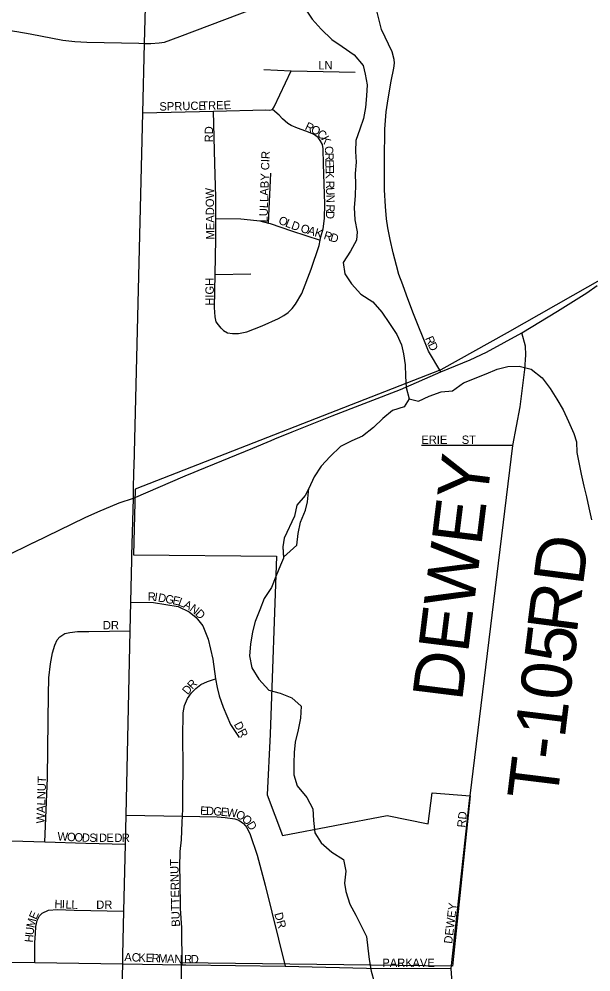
# Model space of a CAD drawing. Extents: x 1857828 to 2277390, y 930619 to 1324581.
# Drawn here: x 2047591 to 2051013, y 1238040 to 1243739 of the extents above; entities that cross this region are included whole.
import ezdxf

# ---------------------------------------------------------------- set-up
doc = ezdxf.new("R2010")
doc.units = 0
for name, color, linetype in [('GM_X_City_Street', 7, 'Continuous'), ('GM_X_City_Street_Text', 7, 'Continuous'), ('GM_X_Corporation', 7, 'Continuous'), ('GM_X_County_Road', 7, 'Continuous'), ('GM_X_Interchange_Ramps', 7, 'Continuous'), ('GM_X_Minor_Lake', 7, 'Continuous'), ('GM_X_Minor_River', 7, 'Continuous'), ('GM_X_State_Route', 7, 'Continuous'), ('GM_X_Township_Road', 7, 'Continuous'), ('GM_X_Township_Road_Text', 7, 'Continuous'), ('GM_X_Township_Subdivision', 7, 'Continuous'), ('GM_X_Township_Subdivision_Text', 7, 'Continuous')]:
    doc.layers.add(name, color=color, linetype=linetype)

msp = doc.modelspace()

# ---------------------------------------------------------------- linework, layer by layer
at = {"layer": 'GM_X_City_Street'}
for points in [[(2050114.3, 1241629.1), (2050041.6, 1241751.9), (2049947.3, 1241986.2), (2049910.3, 1242088.3), (2049887.7, 1242148.4), (2049863.1, 1242210.5), (2049850.6, 1242264.6), (2049829.9, 1242340.8), (2049811.2, 1242421), (2049798.6, 1242489.1), (2049790.1, 1242543.3), (2049783.4, 1242617.6), (2049778.5, 1242717.9), (2049777, 1242896.6), (2049779.4, 1243079.4), (2049788.6, 1243183.9), (2049799.9, 1243262.3), (2049817.1, 1243366.8), (2049834.5, 1243445.3), (2049838.2, 1243475.4), (2049836, 1243497.5), (2049823.6, 1243543.6), (2049760.2, 1243675.7), (2049725, 1243819.8)], [(2048332.3, 1243178.8), (2048755.6, 1243188), (2049068.5, 1243194.8), (2049092.6, 1243193), (2049108.6, 1243197.1), (2049118.4, 1243213.2), (2049218.9, 1243428.8), (2049602, 1243421.5)], [(2049056.3, 1243437.7), (2049218.9, 1243428.8)], [(2048801, 1241889.6), (2048815.1, 1241875.6), (2048839.3, 1241861.8), (2048869.4, 1241857.9), (2048903.5, 1241858.2), (2048953.5, 1241868.6), (2049045.5, 1241903.4), (2049143.4, 1241948.3), (2049175.3, 1241966.6), (2049201.2, 1241982.8), (2049225.1, 1242007.1), (2049245, 1242033.3), (2049282.5, 1242097.9), (2049339.4, 1242242.9), (2049386.3, 1242383.8), (2049393.7, 1242417.1), (2049397.9, 1242436.1), (2049411.5, 1242484.4), (2049419, 1242546.7), (2049420.3, 1242633), (2049412.2, 1242869.9), (2049411.4, 1242962.3), (2049407.2, 1242988.4), (2049392.9, 1243012.4), (2049380.7, 1243030.4), (2049352.5, 1243050.2), (2049308.2, 1243068), (2049257.9, 1243085.7), (2049219.7, 1243101.5), (2049199.5, 1243113.4), (2049167.2, 1243141.3), (2049147, 1243163.2), (2049108.6, 1243197.1)], [(2048801, 1241889.6), (2048784.7, 1241909.6), (2048770.5, 1241927.5), (2048764.3, 1241957.6), (2048761.7, 1242013.8), (2048764.9, 1242210.7), (2048768.3, 1242421.5), (2048769.3, 1242540), (2048769.2, 1242546), (2048768.1, 1242672.5), (2048762.4, 1242875.3), (2048755.6, 1243188)], [(2049084.4, 1242518.7), (2049097.8, 1242817.5)], [(2048769.2, 1242546), (2048917.7, 1242543.1), (2048975.9, 1242537.4), (2049032.1, 1242531.8), (2049084.4, 1242518.7), (2049094.4, 1242516.2), (2049221.1, 1242472.9), (2049393.7, 1242417.1)], [(2048764.9, 1242210.7), (2048978.6, 1242214.1)], [(2050599.4, 1241861.1), (2050813.1, 1241991.1), (2050988.2, 1242101.5), (2051051, 1242145.6)], [(2049100.5, 1241219), (2049121.8, 1241227.9), (2049224.6, 1241270.8), (2049465.7, 1241364.8), (2049873.3, 1241522.8), (2050114.3, 1241629.1), (2050291.1, 1241700.9), (2050387.5, 1241747), (2050599.4, 1241861.1)], [(2048662.4, 1241038.2), (2048989.7, 1241172.8), (2049100.5, 1241219)], [(2047680.6, 1240608.2), (2047987.5, 1240756.7), (2048063.8, 1240790.7), (2048190.3, 1240844.7), (2048275.3, 1240872.4)], [(2046329.7, 1239926.7), (2046368.7, 1239947.8), (2046563.8, 1240050.7), (2046760.3, 1240150.1), (2047028.5, 1240284.5), (2047208, 1240368.8), (2047507.5, 1240524.5), (2047678.9, 1240607.4), (2047680.6, 1240608.2)], [(2048260.5, 1240250.8), (2048395.9, 1240250.1), (2048542.5, 1240225), (2048609, 1240193.4), (2048651.4, 1240159.5), (2048691.9, 1240109.6), (2048722.7, 1240029.5), (2048751.8, 1239909.3), (2048767, 1239792.5), (2048777.4, 1239740.8), (2048787.8, 1239690.6), (2048812.5, 1239622.6), (2048857.5, 1239520.5), (2048908.3, 1239442.5)], [(2047746.6, 1238816.8), (2047761.2, 1239199.3), (2047766.2, 1239542.7), (2047766.9, 1239697.4), (2047770.1, 1239797.8), (2047779.4, 1239882.2), (2047790.8, 1239948.5), (2047806.5, 1239994.9), (2047820.2, 1240025), (2047836.1, 1240043.3), (2047866, 1240063.5), (2047896.1, 1240069.8), (2047942.1, 1240076.1), (2048008.3, 1240076.6), (2048256.7, 1240079.8)], [(2048566.5, 1238082.4), (2048565.1, 1238303.5), (2048558.1, 1238419.9), (2048554.6, 1238588.5), (2048553.9, 1238666.8), (2048555.2, 1238759.2), (2048562.6, 1238829.6), (2048567.7, 1238936), (2048569.2, 1238971.4), (2048571, 1239014.4), (2048572.3, 1239100.7), (2048572.8, 1239273.4), (2048571.3, 1239442.1), (2048574.1, 1239588.7), (2048581.7, 1239632.9), (2048599.4, 1239675.2), (2048623.2, 1239709.5), (2048649.1, 1239735.8), (2048678.9, 1239758.1), (2048718.9, 1239776.5), (2048767, 1239792.5)], [(2050175.8, 1238060.8), (2050286.8, 1239065.8)], [(2048231.9, 1238977.4), (2048569.2, 1238971.4), (2048776, 1238967.7), (2048824.2, 1238964), (2048882.4, 1238956.3), (2048906.5, 1238946.5), (2048934.8, 1238926.6), (2048955.1, 1238902.7), (2048973.4, 1238862.6), (2049016.6, 1238738.4), (2049064.3, 1238558.1), (2049184.5, 1238073.8)], [(2047280.7, 1238830.9), (2047746.6, 1238816.8), (2047991.2, 1238809.4), (2048228, 1238804.4)], [(2047686.1, 1238095.4), (2047685.4, 1238214.8), (2047689, 1238269.1), (2047692.6, 1238311.3), (2047700.3, 1238347.5), (2047714.1, 1238375.7), (2047730, 1238391.8), (2047768, 1238408.2), (2047822.1, 1238412.6), (2047920.4, 1238409.3), (2048218.9, 1238402.8)], [(2044269.9, 1238136.2), (2044270.6, 1238136.2), (2044643.1, 1238131.7), (2044937.6, 1238128.2), (2045323.7, 1238123.6), (2045700.7, 1238119.1), (2046048.1, 1238114.9), (2046166.6, 1238113.5), (2046555.1, 1238108.9), (2047004.4, 1238103.5), (2047317.3, 1238099.8), (2047686.1, 1238095.4), (2048211.9, 1238089.1)], [(2048211.9, 1238089.1), (2048566.5, 1238082.4), (2048589.9, 1238082)], [(2049669.9, 1238061.4), (2050175.8, 1238060.8)]]:
    msp.add_lwpolyline(points, dxfattribs=at)
at = {"layer": 'GM_X_Corporation'}
msp.add_lwpolyline([(2054519.4, 1244972.1), (2052959.6, 1243661.5), (2051504, 1242516), (2051093.4, 1242193.8), (2050512.1, 1241862.8), (2050115.7, 1241640.1), (2048286.1, 1240927.9), (2048275.3, 1240533.9), (2049131.1, 1240525.7), (2049093, 1239461.4), (2049075.6, 1239098), (2049168.6, 1238855), (2049793.9, 1238975.3), (2050039.3, 1238925.1), (2050063.1, 1239111.8), (2050289.8, 1239093.4), (2050184.9, 1238073.5), (2048562, 1238095.1), (2048562, 1237508.6)], dxfattribs=at)
at = {"layer": 'GM_X_County_Road'}
msp.add_lwpolyline([(2048275.3, 1240872.4), (2048586, 1241006.7), (2048638.4, 1241028.3), (2048662.4, 1241038.2)], dxfattribs=at)
at = {"layer": 'GM_X_Interchange_Ramps'}
for points in [[(2048342.5, 1243593.2), (2048380.3, 1243592.3), (2048429.2, 1243595.8), (2048462.6, 1243600.8), (2048554.3, 1243634.7), (2049001.7, 1243803.6), (2049097.6, 1243838.3), (2049191.4, 1243864.8), (2049287.3, 1243889.3), (2049379, 1243905.6), (2049486.7, 1243920.4), (2049481.9, 1243984.8)], [(2047343.5, 1243756.3), (2047352.1, 1243688.2), (2047394.3, 1243687.3), (2047486.1, 1243679.1), (2047577.9, 1243664.8), (2047657.5, 1243650.6), (2047853.3, 1243611.8), (2047924.7, 1243603.6), (2047996.1, 1243599.5), (2048308.3, 1243594), (2048342.5, 1243593.2)]]:
    msp.add_lwpolyline(points, dxfattribs=at)
at = {"layer": 'GM_X_Minor_Lake'}
for points in [[(2049324.8, 1240931.6), (2049303.1, 1240889.2), (2049253.4, 1240830.6), (2049239.9, 1240766.2), (2049176.8, 1240633.2), (2049169.2, 1240582.9), (2049173.5, 1240519.4)], [(2049324.8, 1240931.6), (2049303.1, 1240889.2), (2049253.4, 1240830.6), (2049239.9, 1240766.2), (2049176.8, 1240633.2), (2049169.2, 1240582.9), (2049173.8, 1240514.6)], [(2049173.5, 1240519.4), (2049253.4, 1240591.6), (2049260.9, 1240661.9), (2049276.3, 1240730.3), (2049305.9, 1240800.9), (2049317.5, 1240851.2), (2049324.8, 1240931.6)]]:
    msp.add_lwpolyline(points, dxfattribs=at)
at = {"layer": 'GM_X_Minor_River'}
for points in [[(2049300.3, 1243804.6), (2049345, 1243738.6), (2049399.7, 1243678.6), (2049462.5, 1243616.8), (2049525.1, 1243575), (2049595.8, 1243525.3), (2049650.5, 1243461.4), (2049663, 1243409.2), (2049673.6, 1243345), (2049670.2, 1243278.7), (2049664.7, 1243210.3), (2049653.2, 1243143.9)], [(2049653.2, 1243143.9), (2049629.7, 1243079.5), (2049606.2, 1243013), (2049604.7, 1242946.7), (2049609.3, 1242882.4), (2049601.8, 1242814.1), (2049604.4, 1242749.8), (2049603, 1242681.5), (2049595.6, 1242611.1), (2049600.2, 1242538.8), (2049614.9, 1242466.6), (2049611.3, 1242416.3), (2049573.7, 1242349.8), (2049530.1, 1242283.1), (2049540.7, 1242214.9), (2049581.4, 1242154.9), (2049636.1, 1242093), (2049708.8, 1242047.3), (2049761.5, 1241985.4), (2049808.3, 1241917.4), (2049851, 1241851.4), (2049879.6, 1241789.3), (2049892.1, 1241737.1), (2049900.7, 1241670.9), (2049903.3, 1241602.6), (2049907.9, 1241534.3), (2049924.5, 1241468.1)], [(2049924.5, 1241468.1), (2049980.9, 1241452.4), (2050044.8, 1241483), (2050116.9, 1241509.6), (2050185.1, 1241516.1), (2050250.9, 1241562.8), (2050387, 1241615.9), (2050451, 1241644.5), (2050515.1, 1241661), (2050583.3, 1241663.5), (2050655.8, 1241643.9), (2050720.5, 1241592.1), (2050769.2, 1241530.1), (2050809.9, 1241466.1), (2050846.5, 1241402.1), (2050879.3, 1241332), (2050910, 1241259.9), (2050926.5, 1241209.7), (2050929, 1241145.5), (2050954.2, 1241017.1), (2050970.9, 1240944.8), (2050985.5, 1240880.6), (2051000.1, 1240814.4), (2051016.8, 1240744.2)], [(2049924.5, 1241468.1), (2049894.8, 1241419.7), (2049826.7, 1241397.1), (2049768.9, 1241350.5), (2049711.2, 1241295.9), (2049645.4, 1241243.2), (2049583.4, 1241216.6), (2049515.4, 1241182), (2049453.7, 1241123.3), (2049398, 1241064.7), (2049356.3, 1241000.1), (2049324.8, 1240931.6)], [(2049173.8, 1240514.6), (2049156.1, 1240472.3), (2049128.6, 1240403.8), (2049101, 1240339.4), (2049057.4, 1240272.8), (2049031.9, 1240206.3), (2049004.4, 1240135.8), (2048988.8, 1240073.4), (2048975.4, 1240001), (2048970, 1239930.6), (2048984.7, 1239858.4), (2049025.4, 1239790.3), (2049086.2, 1239724.5), (2049154.6, 1239706.8), (2049223.1, 1239679.2), (2049279.7, 1239629.3), (2049276.3, 1239557), (2049260.8, 1239488.6), (2049243.4, 1239414.1), (2049237.9, 1239351.8), (2049234.5, 1239287.5), (2049235, 1239219.2), (2049255.7, 1239153), (2049312.5, 1239083.1), (2049349.2, 1239015), (2049353.8, 1238944.7), (2049360.5, 1238872.5), (2049399.1, 1238812.4), (2049463.8, 1238756.6), (2049532.5, 1238712.9), (2049547.1, 1238642.7), (2049537.7, 1238570.3), (2049546.2, 1238520.1), (2049570.9, 1238445.9), (2049605.6, 1238379.9), (2049670.9, 1238251.8), (2049677.5, 1238181.5), (2049686.1, 1238113.2), (2049698.8, 1238045), (2049715.4, 1237980.8)]]:
    msp.add_lwpolyline(points, dxfattribs=at)
at = {"layer": 'GM_X_State_Route'}
for points in [[(2048279.2, 1241032.4), (2048280, 1241062.7), (2048332.3, 1243178.8), (2048342.5, 1243593.2), (2048349.7, 1243883.2)], [(2048276.6, 1240925.7), (2048279.2, 1241032.4)], [(2048266.2, 1240504.8), (2048266.8, 1240530.6), (2048275.3, 1240872.4), (2048276.6, 1240925.7)], [(2048213.1, 1238141.6), (2048218.9, 1238402.8), (2048228, 1238804.4), (2048231.9, 1238977.4), (2048256.7, 1240079.8), (2048260.5, 1240250.8), (2048266.2, 1240504.8)], [(2048195.6, 1237502.7), (2048211.9, 1238089.1), (2048213.1, 1238141.6)]]:
    msp.add_lwpolyline(points, dxfattribs=at)
at = {"layer": 'GM_X_Township_Road'}
for points in [[(2050286.8, 1239065.8), (2050289.8, 1239093.4), (2050546.5, 1241188.9), (2050589.5, 1241420.1), (2050617.8, 1241643.7), (2050623.2, 1241731.2), (2050621.9, 1241782.4), (2050599.4, 1241861.1)], [(2048589.9, 1238082), (2049184.5, 1238073.8), (2049669.9, 1238061.4)], [(2050417.1, 1235061.1), (2050295.9, 1235126), (2050203.2, 1235192.5), (2050158.9, 1235238.9), (2050052.1, 1235400.1), (2050005.8, 1235486.7), (2049976.6, 1235543.2), (2049973.5, 1235627.8), (2049979.6, 1235839.4), (2049989.7, 1236004.2), (2050072.2, 1236844), (2050098.5, 1237032.8), (2050146.8, 1237207.3), (2050175, 1237312.9), (2050192.4, 1237414.3), (2050198, 1237519.7), (2050203.5, 1237628.9), (2050196.1, 1237777.9), (2050175.8, 1238060.8)]]:
    msp.add_lwpolyline(points, dxfattribs=at)
at = {"layer": 'GM_X_Township_Subdivision'}
msp.add_lwpolyline([(2050546.5, 1241188.9), (2049999, 1241187.6)], dxfattribs=at)

# ---------------------------------------------------------------- texts
at = {"layer": 'GM_X_City_Street_Text'}
for s, rotation, p in [('LN', 0, (2049381.9, 1243437.3)), ('TREE', 1.6357, (2048682.1, 1243195.3)), ('SPRUCE', 1.1011, (2048431.4, 1243190.9)), ('RD', 90, (2048752.2, 1243001.1)), ('R', 334.0648, (2049297.5, 1243080.3)), ('O', 334.0645, (2049333.1, 1243062.9)), ('C', 319.0563, (2049369.8, 1243045.6)), ('K', 298.8338, (2049396.7, 1243023.3)), ('C', 274.3279, (2049419.7, 1242977.3)), ('LULLABY CIR', 88.1104, (2049077.7, 1242521.8)), ('R', 271.7975, (2049422.6, 1242938.4)), ('E', 271.5031, (2049423.9, 1242898.9)), ('E', 271.5031, (2049424.8, 1242863.7)), ('K', 271.5086, (2049425.7, 1242828.5)), ('R', 271.5137, (2049427.2, 1242771.3)), ('MEADOW', 90.7646, (2048760.9, 1242420.5)), ('U', 271.5136, (2049428.2, 1242731.7)), ('N', 271.3338, (2049429.4, 1242687.8)), ('R', 267.7899, (2049430.4, 1242631.4)), ('D', 267.5522, (2049428.9, 1242591.9)), ('O', 337.2406, (2049139.2, 1242517)), ('L', 337.6341, (2049180.1, 1242499.8)), ('D', 341.4081, (2049216, 1242485.1)), ('O', 342.9905, (2049271.8, 1242466.8)), ('A', 342.9616, (2049313.8, 1242453.9)), ('K', 342.9616, (2049355.9, 1242441)), ('R', 342.9947, (2049410.6, 1242424.2)), ('D', 342.9616, (2049448.5, 1242412.6)), ('HIGH', 90, (2048756.5, 1242024.3)), ('R', 293.0009, (2050019.9, 1241829.7)), ('D', 295.434, (2050036.3, 1241791.2)), ('R', 357.8142, (2048360.6, 1240260.5)), ('I', 351.1342, (2048398.7, 1240259.2)), ('D', 350.2933, (2048420.2, 1240255.8)), ('G', 349.4958, (2048463.4, 1240248.4)), ('E', 347.7793, (2048506.3, 1240240.5)), ('L', 338.5132, (2048538.7, 1240233.6)), ('A', 334.0312, (2048570.5, 1240221.2)), ('N', 323.3618, (2048607.9, 1240203.2)), ('D', 316.0355, (2048641.9, 1240178)), ('DR', 0, (2048092.8, 1240088.9)), ('R', 45.2748, (2048627.9, 1239726.5)), ('D', 49.7354, (2048600.1, 1239693.7)), ('DR', 297.8861, (2048875.4, 1239520.7)), ('WALNUT', 88.0918, (2047744.5, 1238927)), ('E', 357.4855, (2048674, 1238980.1)), ('D', 357.4639, (2048709.1, 1238978.6)), ('G', 356.4564, (2048752.8, 1238976.6)), ('E', 355.0208, (2048796.4, 1238973.9)), ('W', 353.1919, (2048831.1, 1238970.9)), ('O', 334.6569, (2048883.8, 1238965.3)), ('O', 318.479, (2048920.4, 1238948.5)), ('RD', 83.9934, (2050261.4, 1238901.3)), ('D', 301.0462, (2048950.8, 1238922.4)), ('W', 357.0729, (2047820.4, 1238826.1)), ('O', 357.0699, (2047877.6, 1238823.2)), ('O', 357.1216, (2047921.5, 1238820.9)), ('D', 358.3489, (2047966.7, 1238818.7)), ('S', 359.9457, (2048012.2, 1238817.3)), ('I', 359.985, (2048047.4, 1238817.3)), ('D', 359.9929, (2048069.4, 1238817.3)), ('E', 359.9956, (2048113.4, 1238817.3)), ('D', 359.9929, (2048161.8, 1238817.3)), ('R', 359.9941, (2048205.8, 1238817.3)), ('BUTTERNUT', 91.3942, (2048554.1, 1238310.5)), ('H', 357.9016, (2047802.7, 1238421.3)), ('I', 357.8822, (2047846.7, 1238419.7)), ('L', 357.9073, (2047868.7, 1238418.9)), ('L', 358.9128, (2047904.8, 1238417.6)), ('DR', 0, (2048053.2, 1238416.9)), ('E', 66.1735, (2047693.9, 1238349.2)), ('DEWEY', 83.0232, (2050182.2, 1238206.2)), ('M', 76.4497, (2047682.3, 1238300.2)), ('DR', 285.5291, (2049118.2, 1238388)), ('U', 84.4851, (2047678.4, 1238258.2)), ('H', 84.4851, (2047674.1, 1238214.4)), ('A', 357.8142, (2048220.7, 1238104.5)), ('C', 357.8548, (2048264.7, 1238102.8)), ('K', 357.8142, (2048304.3, 1238101.3)), ('E', 357.8557, (2048348.3, 1238099.7)), ('R', 357.8142, (2048383.4, 1238098.4)), ('M', 357.8196, (2048423, 1238096.8)), ('A', 357.8535, (2048475.8, 1238094.8)), ('N', 358.09, (2048520, 1238093.2)), ('R', 359.7567, (2048578.8, 1238091.5)), ('D', 359.9929, (2048618.6, 1238091.3)), ('PARK', 0, (2049764.8, 1238069.3)), ('AVE', 0, (2049945.1, 1238069.3))]:
    msp.add_text(s, height=50, rotation=rotation, dxfattribs=at).set_placement(p)
at = {"layer": 'GM_X_Township_Road_Text'}
for s, rotation, p in [('DEWEY', 82.9459, (2050241.7, 1239654)), ('RD', 82.5687, (2050927.3, 1240056.8)), ('T-105', 82.98, (2050809.5, 1239056.7))]:
    msp.add_text(s, height=300, rotation=rotation, dxfattribs=at).set_placement(p)
at = {"layer": 'GM_X_Township_Subdivision_Text'}
for s, p in [('ERIE', (2049997.9, 1241197.7)), ('ST', (2050239.9, 1241197.7))]:
    msp.add_text(s, height=50, rotation=0, dxfattribs=at).set_placement(p)

doc.saveas('drawing.dxf')
